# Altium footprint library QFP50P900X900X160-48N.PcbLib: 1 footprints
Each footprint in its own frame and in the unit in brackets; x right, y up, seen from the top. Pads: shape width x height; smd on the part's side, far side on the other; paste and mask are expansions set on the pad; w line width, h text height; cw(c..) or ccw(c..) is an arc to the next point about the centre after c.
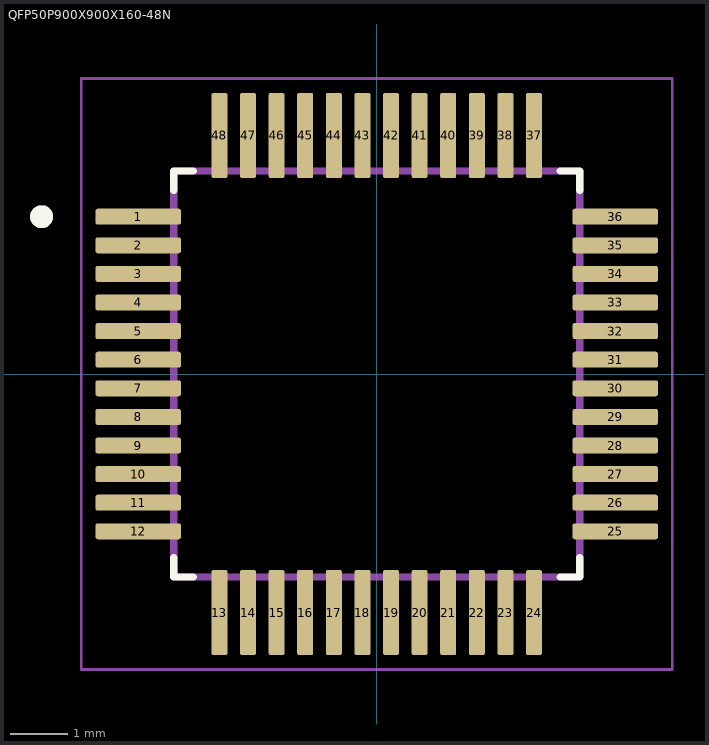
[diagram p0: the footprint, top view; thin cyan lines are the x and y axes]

## QFP50P900X900X160-48N [mm]
pads (48):
  rrect25% 1.49x0.28 smd: 1(-4.17,2.75) 2(-4.17,2.25) 3(-4.17,1.75) 4(-4.17,1.25) 5(-4.17,0.75) 6(-4.17,0.25) 7(-4.17,-0.25) 8(-4.17,-0.75) 9(-4.17,-1.25) 10(-4.17,-1.75) 11(-4.17,-2.25) 12(-4.17,-2.75) 25(4.17,-2.75) 26(4.17,-2.25) 27(4.17,-1.75) 28(4.17,-1.25) 29(4.17,-0.75) 30(4.17,-0.25) 31(4.17,0.25) 32(4.17,0.75) 33(4.17,1.25) 34(4.17,1.75) 35(4.17,2.25) 36(4.17,2.75)
  rrect25% 0.28x1.49 smd: 13(-2.75,-4.17) 14(-2.25,-4.17) 15(-1.75,-4.17) 16(-1.25,-4.17) 17(-0.75,-4.17) 18(-0.25,-4.17) 19(0.25,-4.17) 20(0.75,-4.17) 21(1.25,-4.17) 22(1.75,-4.17) 23(2.25,-4.17) 24(2.75,-4.17) 37(2.75,4.17) 38(2.25,4.17) 39(1.75,4.17) 40(1.25,4.17) 41(0.75,4.17) 42(0.25,4.17) 43(-0.25,4.17) 44(-0.75,4.17) 45(-1.25,4.17) 46(-1.75,4.17) 47(-2.25,4.17) 48(-2.75,4.17)
Top Overlay:
  circle w0.2: c-5.86,2.75 r0.1
  lines w0.127: -3.55,-3.21 -3.55,-3.55 -3.21,-3.55 ; -3.55,3.21 -3.55,3.55 -3.21,3.55 ; 3.21,-3.55 3.55,-3.55 3.55,-3.21 ; 3.21,3.55 3.55,3.55 3.55,3.21
Mechanical 13:
  circle w0.2: c-5.86,2.75 r0.1
  lines w0.127: -3.55,-3.55 -3.55,3.55 3.55,3.55 3.55,-3.55 -3.55,-3.55
Mechanical 15:
  lines w0.05: -5.165,-5.165 -5.165,5.165 5.165,5.165 5.165,-5.165 -5.165,-5.165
